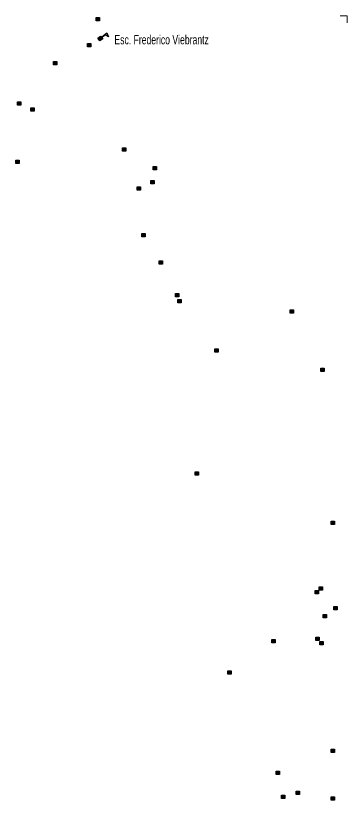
# Model space of a CAD drawing. Extents: x 649.2 to 674.4, y 7040 to 7068.1.
# Drawn here: x 671.52 to 674.4, y 7060.92 to 7067.74 of the extents above; entities that cross this region are included whole.
import ezdxf

# ---------------------------------------------------------------- set-up
doc = ezdxf.new("R2010")
doc.units = 0
doc.header["$LTSCALE"] = 0.032
for name, color, linetype, lineweight in [('2', 7, 'Continuous', 25), ('4', 7, 'Continuous', 25), ('63', 7, 'Continuous', 13)]:
    doc.layers.add(name, color=color, linetype=linetype, lineweight=lineweight)
doc.layers.add('61', color=7, linetype='Continuous')

msp = doc.modelspace()

# ---------------------------------------------------------------- hatches: boundary and pattern name
at = {"layer": '2'}
for points in [[(672.219, 7067.7303), (672.248, 7067.7303), (672.248, 7067.7013), (672.219, 7067.7013)], [(672.1432, 7067.5044), (672.1722, 7067.5044), (672.1722, 7067.4754), (672.1432, 7067.4754)], [(671.8475, 7067.3455), (671.8765, 7067.3455), (671.8765, 7067.3165), (671.8475, 7067.3165)], [(671.5356, 7066.9963), (671.5646, 7066.9963), (671.5646, 7066.9673), (671.5356, 7066.9673)], [(671.6509, 7066.9438), (671.6799, 7066.9438), (671.6799, 7066.9148), (671.6509, 7066.9148)], [(672.4468, 7066.5949), (672.4758, 7066.5949), (672.4758, 7066.5659), (672.4468, 7066.5659)], [(671.5188, 7066.4894), (671.5478, 7066.4894), (671.5478, 7066.4604), (671.5188, 7066.4604)], [(672.7143, 7066.4332), (672.7433, 7066.4332), (672.7433, 7066.4042), (672.7143, 7066.4042)], [(672.6927, 7066.3127), (672.7217, 7066.3127), (672.7217, 7066.2837), (672.6927, 7066.2837)], [(672.5742, 7066.2559), (672.6032, 7066.2559), (672.6032, 7066.2269), (672.5742, 7066.2269)], [(672.6133, 7065.8509), (672.6423, 7065.8509), (672.6423, 7065.8219), (672.6133, 7065.8219)], [(672.7666, 7065.615), (672.7956, 7065.615), (672.7956, 7065.586), (672.7666, 7065.586)], [(672.9063, 7065.331), (672.9353, 7065.331), (672.9353, 7065.302), (672.9063, 7065.302)], [(672.9273, 7065.2785), (672.9563, 7065.2785), (672.9563, 7065.2495), (672.9273, 7065.2495)], [(673.9034, 7065.1884), (673.9324, 7065.1884), (673.9324, 7065.1594), (673.9034, 7065.1594)], [(673.2503, 7064.8478), (673.2793, 7064.8478), (673.2793, 7064.8188), (673.2503, 7064.8188)], [(674.1685, 7064.6815), (674.1975, 7064.6815), (674.1975, 7064.6525), (674.1685, 7064.6525)], [(673.0775, 7063.7798), (673.1065, 7063.7798), (673.1065, 7063.7508), (673.0775, 7063.7508)], [(674.2608, 7063.3512), (674.2898, 7063.3512), (674.2898, 7063.3222), (674.2608, 7063.3222)], [(674.1196, 7062.7474), (674.1486, 7062.7474), (674.1486, 7062.7184), (674.1196, 7062.7184)], [(674.1555, 7062.78), (674.1845, 7062.78), (674.1845, 7062.751), (674.1555, 7062.751)], [(674.2835, 7062.6071), (674.3125, 7062.6071), (674.3125, 7062.5781), (674.2835, 7062.5781)], [(674.1892, 7062.5374), (674.2182, 7062.5374), (674.2182, 7062.5084), (674.1892, 7062.5084)], [(674.1263, 7062.3409), (674.1553, 7062.3409), (674.1553, 7062.3119), (674.1263, 7062.3119)], [(673.7445, 7062.3207), (673.7735, 7062.3207), (673.7735, 7062.2917), (673.7445, 7062.2917)], [(674.1611, 7062.305), (674.1901, 7062.305), (674.1901, 7062.276), (674.1611, 7062.276)], [(673.3623, 7062.049), (673.3913, 7062.049), (673.3913, 7062.02), (673.3623, 7062.02)], [(674.2604, 7061.3693), (674.2894, 7061.3693), (674.2894, 7061.3403), (674.2604, 7061.3403)], [(673.7808, 7061.176), (673.8098, 7061.176), (673.8098, 7061.147), (673.7808, 7061.147)], [(673.9562, 7061.0042), (673.9852, 7061.0042), (673.9852, 7060.9752), (673.9562, 7060.9752)], [(673.8274, 7060.9667), (673.8564, 7060.9667), (673.8564, 7060.9377), (673.8274, 7060.9377)], [(674.2587, 7060.9523), (674.2877, 7060.9523), (674.2877, 7060.9233), (674.2587, 7060.9233)]]:
    msp.add_hatch(color=256, dxfattribs=at).paths.add_polyline_path(points)
at = {"layer": '4'}
msp.add_hatch(color=256, dxfattribs=at).paths.add_polyline_path([(672.2322, 7067.5483), (672.2555, 7067.5673), (672.2745, 7067.5441), (672.2512, 7067.5251)])

# ---------------------------------------------------------------- linework, layer by layer
at = {"layer": '2'}
for points in [[(672.219, 7067.7303), (672.248, 7067.7303), (672.248, 7067.7013), (672.219, 7067.7013)], [(672.1432, 7067.5044), (672.1722, 7067.5044), (672.1722, 7067.4754), (672.1432, 7067.4754)], [(671.8475, 7067.3455), (671.8765, 7067.3455), (671.8765, 7067.3165), (671.8475, 7067.3165)], [(671.5356, 7066.9963), (671.5646, 7066.9963), (671.5646, 7066.9673), (671.5356, 7066.9673)], [(671.6509, 7066.9438), (671.6799, 7066.9438), (671.6799, 7066.9148), (671.6509, 7066.9148)], [(672.4468, 7066.5949), (672.4758, 7066.5949), (672.4758, 7066.5659), (672.4468, 7066.5659)], [(671.5188, 7066.4894), (671.5478, 7066.4894), (671.5478, 7066.4604), (671.5188, 7066.4604)], [(672.7143, 7066.4332), (672.7433, 7066.4332), (672.7433, 7066.4042), (672.7143, 7066.4042)], [(672.6927, 7066.3127), (672.7217, 7066.3127), (672.7217, 7066.2837), (672.6927, 7066.2837)], [(672.5742, 7066.2559), (672.6032, 7066.2559), (672.6032, 7066.2269), (672.5742, 7066.2269)], [(672.6133, 7065.8509), (672.6423, 7065.8509), (672.6423, 7065.8219), (672.6133, 7065.8219)], [(672.7666, 7065.615), (672.7956, 7065.615), (672.7956, 7065.586), (672.7666, 7065.586)], [(672.9063, 7065.331), (672.9353, 7065.331), (672.9353, 7065.302), (672.9063, 7065.302)], [(672.9273, 7065.2785), (672.9563, 7065.2785), (672.9563, 7065.2495), (672.9273, 7065.2495)], [(673.9034, 7065.1884), (673.9324, 7065.1884), (673.9324, 7065.1594), (673.9034, 7065.1594)], [(673.2503, 7064.8478), (673.2793, 7064.8478), (673.2793, 7064.8188), (673.2503, 7064.8188)], [(674.1685, 7064.6815), (674.1975, 7064.6815), (674.1975, 7064.6525), (674.1685, 7064.6525)], [(673.0775, 7063.7798), (673.1065, 7063.7798), (673.1065, 7063.7508), (673.0775, 7063.7508)], [(674.2608, 7063.3512), (674.2898, 7063.3512), (674.2898, 7063.3222), (674.2608, 7063.3222)], [(674.1196, 7062.7474), (674.1486, 7062.7474), (674.1486, 7062.7184), (674.1196, 7062.7184)], [(674.1555, 7062.78), (674.1845, 7062.78), (674.1845, 7062.751), (674.1555, 7062.751)], [(674.2835, 7062.6071), (674.3125, 7062.6071), (674.3125, 7062.5781), (674.2835, 7062.5781)], [(674.1892, 7062.5374), (674.2182, 7062.5374), (674.2182, 7062.5084), (674.1892, 7062.5084)], [(674.1263, 7062.3409), (674.1553, 7062.3409), (674.1553, 7062.3119), (674.1263, 7062.3119)], [(673.7445, 7062.3207), (673.7735, 7062.3207), (673.7735, 7062.2917), (673.7445, 7062.2917)], [(674.1611, 7062.305), (674.1901, 7062.305), (674.1901, 7062.276), (674.1611, 7062.276)], [(673.3623, 7062.049), (673.3913, 7062.049), (673.3913, 7062.02), (673.3623, 7062.02)], [(674.2604, 7061.3693), (674.2894, 7061.3693), (674.2894, 7061.3403), (674.2604, 7061.3403)], [(673.7808, 7061.176), (673.8098, 7061.176), (673.8098, 7061.147), (673.7808, 7061.147)], [(673.9562, 7061.0042), (673.9852, 7061.0042), (673.9852, 7060.9752), (673.9562, 7060.9752)], [(673.8274, 7060.9667), (673.8564, 7060.9667), (673.8564, 7060.9377), (673.8274, 7060.9377)], [(674.2587, 7060.9523), (674.2877, 7060.9523), (674.2877, 7060.9233), (674.2587, 7060.9233)]]:
    msp.add_lwpolyline(points, close=True, dxfattribs=at)
at = {"layer": '4'}
msp.add_line((672.2634, 7067.5576), (672.2665, 7067.5538), dxfattribs=at)
for points in [[(672.2634, 7067.5576), (672.3118, 7067.5972), (672.3242, 7067.5622), (672.2971, 7067.5788), (672.2665, 7067.5538)], [(672.2322, 7067.5483), (672.2555, 7067.5673), (672.2745, 7067.5441), (672.2512, 7067.5251)]]:
    msp.add_lwpolyline(points, close=True, dxfattribs=at)
at = {"layer": '63'}
msp.add_lwpolyline([(674.3998, 7067.6833), (674.3998, 7067.7449), (674.3391, 7067.7449)], dxfattribs=at)

# ---------------------------------------------------------------- texts
at = {"layer": '61', "width": 0.7}
msp.add_text('Esc. Frederico Viebrantz', height=0.08, dxfattribs=at).set_placement((672.3766, 7067.4959))

doc.saveas('drawing.dxf')
